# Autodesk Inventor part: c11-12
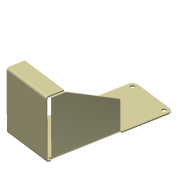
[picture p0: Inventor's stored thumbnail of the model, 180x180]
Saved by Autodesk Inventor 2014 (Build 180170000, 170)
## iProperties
Created: 2011-01
Part Number: c11-12
Material: Steel, Mild
Document SubType Name: Sheet Metal
Designer: Thom Tremblay
Density: 7.86 g/cm^3
Sheet Metal Rule: Steel - 16ga
Appearance: Nylon 6
Author: Thom Tremblay
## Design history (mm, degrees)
sketch "Sketch1"
  geometry: L1 (-72.551, 64.215)-(-72.551, 124.215); L2 (-5.2, 64.215)-(-5.2, 124.215); L3 (0, 65.539)-(75, 65.539); L4 (133.476, 70.215)-(133.476, 118.215); L5 (76.524, 64.215)-(127.476, 64.215); L6 (0, 0)-(0, 67.263); L7 (75, 67.263)-(75, 30.34); L8 (75, 30.34)-(15, 0); L9 (15, 0)-(0, 0); L10 (-1.524, 67.263)-(-1.524, 64.215); L11 (76.524, 64.215)-(76.524, 67.263); L12 (-91.226, 64.215)-(-1.524, 64.215); L13 (127.476, 124.215)-(-91.226, 124.215); L14 (-91.226, 124.215)-(-91.226, 64.215); C1 r 2.553 at (127.476, 118.215); C2 r 2.553 at (127.476, 70.215); A1 r 6 centre (127.476, 118.215) between (133.476, 118.215) and (127.476, 124.215); A2 r 6 centre (127.476, 70.215) between (127.476, 64.215) and (133.476, 70.215); A3 r 0.762 centre (-0.762, 67.263) between (0, 67.263) and (-1.524, 67.263); A4 r 0.762 centre (75.762, 67.263) between (76.524, 67.263) and (75, 67.263); 10 further points
  constraints: 28 end point, 8 point on circle, 6 centre point, 6 point on line, 3 other
node "Face1"
feature "Fold1" dims "d1" = 1.524 (= BendReliefWidth), "d2" = 0.762 (= BendReliefDepth), "d3" = 3.048 (= MinimumRemnant), "d4" = 1.524 (= BendRadius), "d5" = 90 deg, "d6" = 1.524 (= BendRadius), "SeamGap" = 0.01, "Thickness" = 1.524 (derived)
feature "Fold2" dims "d7" = 1.524 (= BendReliefWidth), "d8" = 0.762 (= BendReliefDepth), "d9" = 3.048 (= MinimumRemnant), "d10" = 1.524 (= BendRadius), "d11" = 90 deg, "d12" = 1.524 (= BendRadius), "SeamGap" = 0.01, "Thickness" = 1.524 (derived)
feature "Fold3" dims "d13" = 1.524 (= BendReliefWidth), "d14" = 0.762 (= BendReliefDepth), "d15" = 3.048 (= MinimumRemnant), "d16" = 1.524 (= BendRadius), "d17" = 90 deg, "d18" = 1.524 (= BendRadius), "SeamGap" = 0.01, "Thickness" = 1.524 (derived)
body "Solid1"
face "Plate1" dims "Thickness" = 1.524 (derived)
other parameters: "BendRadius" = 1.524 (= Thickness), "BendReliefWidth" = 1.524 (= Thickness), "BendReliefDepth" = 0.762 (= 0.5 x Thickness), "CornerReliefSize" = 6.096 (= 4 x Thickness), "MinimumRemnant" = 3.048 (= 2 x Thickness), "TransitionRadius" = 1.524 (= BendRadius), "JacobiRadiusSize" = 1.524 (= BendRadius), "GapSize" = 0.762 (= 0.5 x Thickness), "d0" = 1.524 (= BendRadius)
